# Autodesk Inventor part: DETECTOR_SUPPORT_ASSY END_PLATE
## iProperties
Shininess: 64.0
Length Units: 11272
Angle Units: 11279
Time Units: 11290
Mass Units: 11286
Length Display Precision: 3
Angle Display Precision: 2
Compacted: True
Part Number: DETECTOR_SUPPORT_ASSY END_PLATE
Document SubType Name: Modeling
Created: 2004-08
Designer: John Blackburn
Material: MILD_STEEL
Manufacturer: Standard
Standards Organization: Custom
Density: 0.0
Volumn: 0.0
Area: 0.0
PropertySet Name: Model Information
Control State: 0
Master: False
Checked Out: False
Author: John Blackburn
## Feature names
1. ExtrusionBlind1
2. ExtrusionThru1
